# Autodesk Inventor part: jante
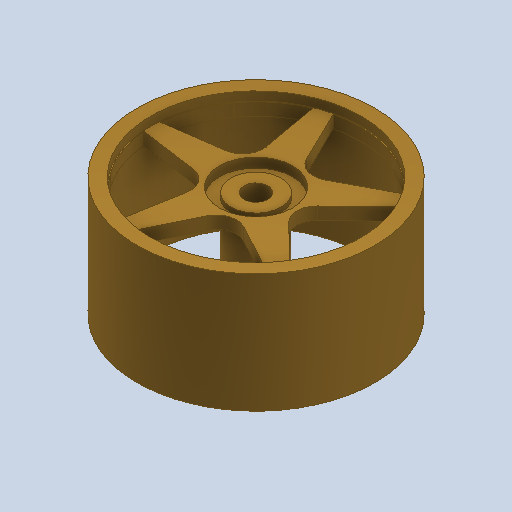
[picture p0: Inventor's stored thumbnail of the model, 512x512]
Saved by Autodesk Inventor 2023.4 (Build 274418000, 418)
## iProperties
Created: 2018-03
Part Number: jante
Material: Laiton, jaune doux
Document SubType Name: Modeling
Designer: Bruno
Density: 8.47 g/cm^3
Appearance: Laiton - Satiné
Author: Bruno
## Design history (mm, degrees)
sketch "Esquisse1"
  geometry: L1 (0, 0)-(5.5, 0); L2 (5.5, -30)-(0, -30); L3 (0, -30)-(0, 0); L4 (26, 0)-(23, 0); L5 (23, -26)-(26, -26); L6 (26, -26)-(26, 0); L7 (23, -1.915)-(5.5, -1.915); L8 (5.5, -4.65)-(23, -4.65); L9 (23, 0)-(23, -1.915); L10 (23, -4.65)-(23, -26); L11 (5.5, 0)-(5.5, -1.915); L12 (5.5, -4.65)-(5.5, -30)
  constraints: 24 end point, 7 parallel, 4 perpendicular, 3 horizontal
  dimensions: "d0" = 5.5 distance of L2.start L2.end; "d1" = 30 distance of L1.end L2.start; "d2" = 3 distance of L5.end L5.start; "d3" = 26 distance of L5.start L4.end; "d4" = 26 distance between parallel lines of L3 L6
revolve "Révolution1" sketch "Esquisse1" stored, may be unused: angle "d5" = 90 deg
sketch "Esquisse2"
  geometry: L1 (2, 1.661)-(2, -1.661); L2 (-2, 1.661)-(-2, -1.661); A1 r 2.6 centre (0, 0) between (2, 1.661) and (-2, 1.661); A2 r 2.6 centre (0, 0) between (-2, -1.661) and (2, -1.661); 1 further point
  constraints: 4 end point, 4 point on circle, 2 centre point, 1 coincident, 1 parallel, 1 vertical
  dimensions: "d7" = 2 distance from line of L1 point (0, 0); "d8" = 2 distance from line of point (0, 0) L2
extrude "Extrusion1" cut sketch "Esquisse2" distance "d9" = 10; taper "d10" = 0 deg
sketch "Esquisse3"
  geometry: L1 (10.34, 3.111)-(19.446, 11.883); L2 (14.525, -0.048)-(22.789, -0.048); L3 (14.525, -0.048)-(8.997, -0.048); A1 r 4.386 centre (13.383, -0.048) between (10.34, 3.111) and (8.997, -0.048); A2 r 22.789 centre (0, 0) between (19.446, 11.883) and (22.789, -0.048); 1 further point
  constraints: 6 end point, 4 point on circle, 2 centre point, 2 horizontal, 1 coincident, 1 tangent
extrude "Extrusion2" cut sketch "Esquisse3" distance "d11" = 10; taper "d12" = 0 deg
mirror "Symétrie1"
pattern_circular "Réseau circulaire1" dims angle "d14" = 360 deg
sketch "Esquisse4"
  geometry: C1 r 8 at (0, 0); 1 further point
  constraints: 1 centre point, 1 coincident
  dimensions: "d16" = 16 diameter of C1
extrude "Extrusion3" cut sketch "Esquisse4" distance "d17" = 4; taper "d18" = 0 deg
sketch "Esquisse5"
  geometry: C1 r 5.5 at (0, 0); 1 further point
  constraints: 1 centre point, 1 coincident
extrude "Extrusion4" join sketch "Esquisse5" distance "d19" = 1; taper "d20" = 0 deg
sketch "Esquisse6"
  geometry: C1 r 2.6 at (0, 0); A1 r 2.6 centre (0, 0) between (-2, -1.661) and (2, -1.661) reference; 3 further points
  constraints: 1 centre point, 1 coincident, 1 concentric
extrude "Extrusion5" cut sketch "Esquisse6" extent not by distance; stored distance "d21" = 0; taper "d22" = 0 deg
node "Solide1"
other parameters: "d6" = 5.2
